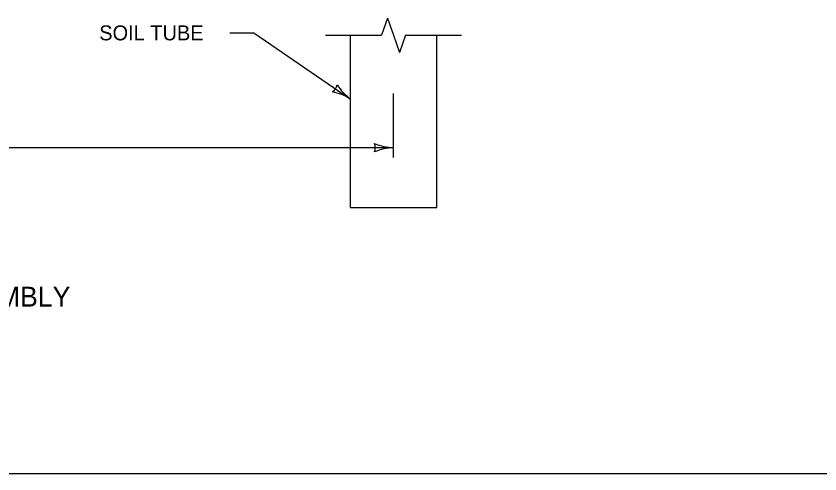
# Model space of a CAD drawing. Extents: x 49991.4 to 50021, y 49987.6 to 50011.4.
# Drawn here: x 50007.796 to 50011.023, y 49987.799 to 49989.638 of the extents above; entities that cross this region are included whole.
import ezdxf

# ---------------------------------------------------------------- set-up
doc = ezdxf.new("R2010")
doc.units = 0
for name, color, linetype in [('Level 1', 7, 'Continuous'), ('Level 2', 7, 'Continuous'), ('Level 3', 7, 'Continuous'), ('Level 4', 7, 'Continuous'), ('Level 6', 7, 'Continuous')]:
    doc.layers.add(name, color=color, linetype=linetype)

msp = doc.modelspace()

# ---------------------------------------------------------------- linework, layer by layer
at = {"layer": 'Level 1'}
msp.add_lwpolyline([(49999.3835, 49998.9992), (50016.7501, 49998.9992), (50016.7501, 49987.7988), (49999.3835, 49987.7988)], close=True, dxfattribs=at)
at = {"layer": 'Level 3'}
for p, q in [((50009.3114, 49989.0692), (50009.3114, 49989.3274)), ((50009.3114, 49989.1092), (50005.284, 49989.1092))]:
    msp.add_line(p, q, dxfattribs=at)
for points in [[(50008.6546, 49989.5705), (50008.7501, 49989.5705)], [(50008.7501, 49989.5705), (50009.1384, 49989.3047)]]:
    msp.add_lwpolyline(points, dxfattribs=at)
for centre, radius, start, end in [((50009.0326, 49989.3771), 0.0548, 307.7463, 343.4687), ((50009.2714, 49989.4828), 0.2223, 213.0635, 233.247), ((50009.0164, 49989.1062), 0.233, 58.4348, 77.6847), ((50009.3205, 49989.3313), 0.2223, 247.456, 267.6395), ((50009.1832, 49989.1092), 0.0548, 342.1388, 17.8612), ((50009.3229, 49988.8765), 0.233, 92.8273, 112.0772)]:
    msp.add_arc(centre, radius, start, end, dxfattribs=at)
at = {"layer": 'Level 4'}
for p, q in [((50009.1384, 49988.8692), (50009.1384, 49989.5608)), ((50009.4845, 49988.8692), (50009.4845, 49989.5608)), ((50009.1384, 49988.8692), (50009.4845, 49988.8692))]:
    msp.add_line(p, q, dxfattribs=at)
at = {"layer": 'Level 6'}
for p, q in [((50009.287, 49989.6294), (50009.2627, 49989.5608)), ((50009.287, 49989.6294), (50009.3113, 49989.5608)), ((50009.0384, 49989.5608), (50009.2627, 49989.5608)), ((50009.3113, 49989.5608), (50009.3356, 49989.4922)), ((50009.3599, 49989.5608), (50009.3356, 49989.4922)), ((50009.3599, 49989.5608), (50009.5845, 49989.5608))]:
    msp.add_line(p, q, dxfattribs=at)

# ---------------------------------------------------------------- texts
at = {"layer": 'Level 2'}
for s, height, p in [('SOIL TUBE ', 0.06, (50008.1298, 49989.5404)), ('END ANCHORAGE ASSEMBLY', 0.08, (50006.4625, 49988.471))]:
    msp.add_text(s, height=height, dxfattribs=at).set_placement(p)

doc.saveas('drawing.dxf')
